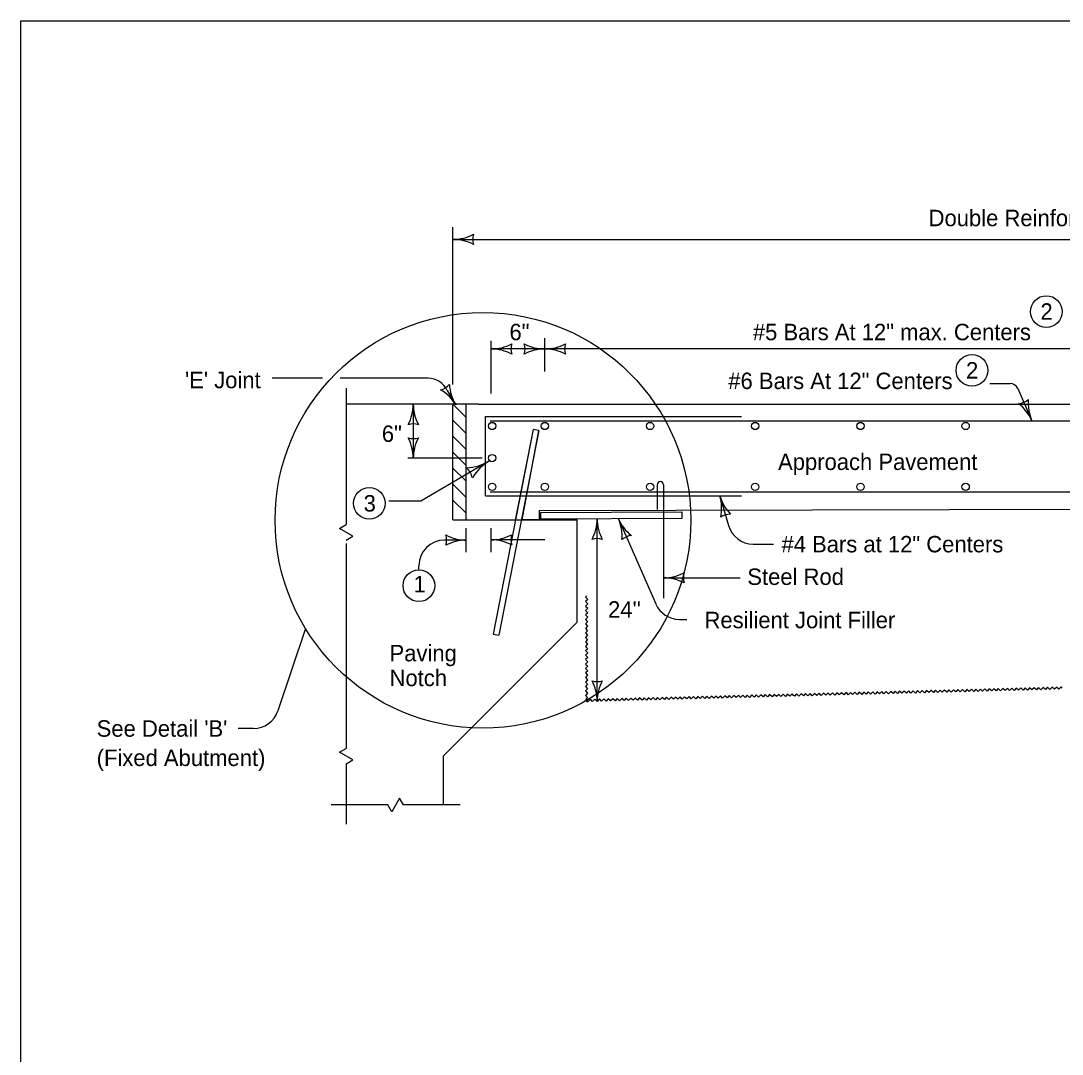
# Model space of a CAD drawing. Extents: x -2134934 to -2124557, y -2139046 to -2134021.
# Drawn here: x -2134934 to -2133922, y -2138041 to -2137036 of the extents above; entities that cross this region are included whole.
import ezdxf

# ---------------------------------------------------------------- set-up
doc = ezdxf.new("R2010")
doc.units = 0
for name, color, linetype in [('BridgeSuperStructureExisting', 7, 'Continuous'), ('dsnAlignmentStation', 7, 'Continuous'), ('dsnCellElements', 7, 'Continuous'), ('dsnStdLabel', 7, 'Continuous'), ('dsnTextFinalPlan', 7, 'Continuous')]:
    doc.layers.add(name, color=color, linetype=linetype)

msp = doc.modelspace()

# ---------------------------------------------------------------- linework, layer by layer
at = {"layer": 'BridgeSuperStructureExisting'}
for p, q in [((-2134618.2, -2137393.1), (-2134618.2, -2137432.3)), ((-2134519.9, -2137395.6), (-2134511.6, -2137409.3)), ((-2134489.3, -2137408.7), (-2134618.2, -2137408.7)), ((-2134514.3, -2137521.3), (-2134514.3, -2137408.7)), ((-2134501.4, -2137421.6), (-2134514.3, -2137408.7)), ((-2134489.3, -2137408.7), (-2133870.3, -2137408.7)), ((-2134501.4, -2137437.2), (-2134514.3, -2137424.3)), ((-2134482.7, -2137420.8), (-2134233.8, -2137420.8)), ((-2134482.7, -2137498), (-2134482.7, -2137420.8)), ((-2134478.1, -2137425), (-2133870.3, -2137425)), ((-2134618.2, -2137432.3), (-2134618.2, -2137525.8)), ((-2134501.4, -2137452.7), (-2134514.3, -2137439.9)), ((-2134501.4, -2137468.3), (-2134514.3, -2137455.4)), ((-2134501.4, -2137483.8), (-2134514.3, -2137471)), ((-2134501.4, -2137499.4), (-2134514.3, -2137486.5)), ((-2134482.7, -2137498), (-2134233.8, -2137498)), ((-2134478.1, -2137494), (-2133870.3, -2137494)), ((-2134501.4, -2137514.9), (-2134514.3, -2137502.1)), ((-2133870.3, -2137511), (-2134430.5, -2137512.5)), ((-2134428.7, -2137514), (-2134291.8, -2137513.5)), ((-2134428.7, -2137520.5), (-2134428.7, -2137514)), ((-2134291.8, -2137513.5), (-2134291.8, -2137520)), ((-2134514.3, -2137521.3), (-2134393.5, -2137521.3)), ((-2134291.8, -2137520), (-2134428.7, -2137520.5)), ((-2134393.5, -2137620.9), (-2134393.5, -2137521.3)), ((-2134618.2, -2137544.4), (-2134618.2, -2137743.5)), ((-2134523.4, -2137750.7), (-2134393.5, -2137620.9)), ((-2134523.4, -2137798.6), (-2134523.4, -2137750.7)), ((-2134618.2, -2137758.6), (-2134618.2, -2137817.4)), ((-2134577.5, -2137798.6), (-2134632.6, -2137798.6)), ((-2134507.3, -2137798.6), (-2134562.4, -2137798.6))]:
    msp.add_line(p, q, dxfattribs=at)
for points in [[(-2134618.2, -2137541), (-2134611.6, -2137537.2), (-2134624.7, -2137529.6), (-2134618.2, -2137525.9)], [(-2134618.2, -2137758.6), (-2134611.6, -2137754.8), (-2134624.7, -2137747.3), (-2134618.2, -2137743.5)], [(-2134562.4, -2137798.6), (-2134566.2, -2137792), (-2134573.8, -2137805.1), (-2134577.5, -2137798.6)]]:
    msp.add_lwpolyline(points, dxfattribs=at)
for centre, radius in [((-2133937.2, -2137318.7), 15.4), ((-2134009.6, -2137375.9), 15.4), ((-2134476.1, -2137430), 3.55), ((-2134424.9, -2137430), 3.55), ((-2134322.6, -2137430), 3.55), ((-2134220.3, -2137430), 3.55), ((-2134118, -2137430), 3.55), ((-2134015.7, -2137430), 3.55), ((-2134476.1, -2137489.1), 3.55), ((-2134424.9, -2137489.1), 3.55), ((-2134322.6, -2137489.1), 3.55), ((-2134220.3, -2137489.1), 3.55), ((-2134118, -2137489.1), 3.55), ((-2134015.7, -2137489.1), 3.55), ((-2134595.5, -2137505.2), 15.4), ((-2134547.4, -2137585.4), 15.4)]:
    msp.add_circle(centre, radius, dxfattribs=at)
for centre, radius, start, end in [((-2133965.9, -2137391.5), 16.9, 275.9068, 311.3735), ((-2133911.3, -2137407.5), 43.6, 175.5676, 203.6401), ((-2133991.2, -2137442.5), 43.6, 23.6401, 51.7126), ((-2134503.2, -2137422.2), 48.4, 272.4041, 300.4766), ((-2134454.1, -2137505.6), 48.4, 120.4766, 148.5491), ((-2134513.6, -2137484.5), 18.7, 12.7432, 48.2099), ((-2134222.3, -2137519.8), 25, 196.3264, 270), ((-2134522.4, -2137566), 25, 90, 180), ((-2134294.1, -2137593.1), 25, 203.6401, 270), ((-2134374, -2137662.2), 16.4, 252.2666, 287.7333), ((-2134416.5, -2137697.8), 42.5, 360, 28.0725), ((-2134331.5, -2137697.8), 42.5, 151.9275, 180), ((-2134708.2, -2137699.2), 25, 270, 341.4058)]:
    msp.add_arc(centre, radius, start, end, dxfattribs=at)
at = {"layer": 'dsnAlignmentStation'}
msp.add_lwpolyline([(-2134934.4, -2137035.9), (-2131799.4, -2137035.9), (-2131799.4, -2139045.9), (-2134934.4, -2139045.9)], close=True, dxfattribs=at)
at = {"layer": 'dsnCellElements'}
for centre, radius, start, end in [((-2134514.3, -2137206), 42.5, 270, 298.0725), ((-2134478.6, -2137248.5), 16.4, 162.2666, 197.7334), ((-2134514.3, -2137291), 42.5, 61.9275, 90), ((-2134477.1, -2137312.6), 42.5, 270, 298.0725), ((-2134477.1, -2137397.6), 42.5, 61.9275, 90), ((-2134441.5, -2137355.1), 16.4, 162.2666, 197.7334), ((-2134460.5, -2137355.1), 16.4, 342.2666, 17.7333), ((-2134424.9, -2137312.6), 42.5, 241.9275, 270), ((-2134424.9, -2137397.6), 42.5, 90, 118.0725), ((-2134424.9, -2137312.6), 42.5, 270, 298.0725), ((-2134424.9, -2137397.6), 42.5, 61.9275, 90), ((-2134389.3, -2137355.1), 16.4, 162.2666, 197.7334), ((-2134530.2, -2137378.9), 16.4, 283.7115, 319.1782), ((-2134547.8, -2137431.4), 42.5, 31.4449, 59.5174), ((-2134475.3, -2137387.1), 42.5, 183.3724, 211.4449), ((-2134595.3, -2137408.7), 42.5, 331.9275, 360), ((-2134510.3, -2137408.7), 42.5, 180, 208.0725), ((-2134552.8, -2137444.4), 16.4, 72.2666, 107.7334), ((-2134552.8, -2137425.8), 16.4, 252.2666, 287.7333), ((-2134595.3, -2137461.4), 42.5, 360, 28.0725), ((-2134510.3, -2137461.4), 42.5, 151.9275, 180), ((-2134213.9, -2137486.1), 42.5, 196.3264, 224.3989), ((-2134295.5, -2137509.9), 42.5, 348.2539, 16.3264), ((-2134244.7, -2137532.2), 16.4, 88.5931, 124.0598), ((-2134416.5, -2137520.3), 42.5, 331.9275, 360), ((-2134331.5, -2137520.3), 42.5, 180, 208.0725), ((-2134314.4, -2137503.2), 42.5, 203.6401, 231.7126), ((-2134392.3, -2137537.2), 42.5, 355.5676, 23.6401), ((-2134536.8, -2137541), 16.4, 342.2666, 17.7333), ((-2134501.2, -2137498.5), 42.5, 241.9275, 270), ((-2134477.1, -2137498.2), 42.5, 270, 298.0725), ((-2134441.5, -2137540.7), 16.4, 162.2666, 197.7334), ((-2134339, -2137552.8), 16.4, 95.9068, 131.3735), ((-2134501.2, -2137583.5), 42.5, 90, 118.0725), ((-2134477.1, -2137583.2), 42.5, 61.9275, 90), ((-2134374, -2137555.9), 16.4, 72.2666, 107.7334), ((-2134309.4, -2137535.1), 42.5, 270, 298.0725), ((-2134309.4, -2137620.1), 42.5, 61.9275, 90), ((-2134273.8, -2137577.6), 16.4, 162.2666, 197.7334)]:
    msp.add_arc(centre, radius, start, end, dxfattribs=at)
at = {"layer": 'dsnStdLabel'}
for p, q in [((-2134514.3, -2137355.4), (-2134514.3, -2137236.5)), ((-2134514.3, -2137248.5), (-2133142.6, -2137248.5)), ((-2134424.9, -2137377.1), (-2134424.9, -2137344.5)), ((-2134514.3, -2137389.8), (-2134514.3, -2137355.4)), ((-2134477.1, -2137398.4), (-2134477.1, -2137347.2)), ((-2134424.9, -2137355.1), (-2134477.1, -2137355.1)), ((-2133854.6, -2137355.1), (-2134424.9, -2137355.1)), ((-2134681.1, -2137383.5), (-2134690, -2137383.5)), ((-2134641.2, -2137383.5), (-2134681.1, -2137383.5)), ((-2134538.4, -2137383.5), (-2134623.8, -2137383.5)), ((-2133992.3, -2137388.7), (-2133972.5, -2137388.7)), ((-2133965, -2137393.5), (-2133951.3, -2137425)), ((-2134552.8, -2137408.7), (-2134552.8, -2137461.4)), ((-2134501.4, -2137521.3), (-2134501.4, -2137408.7)), ((-2134501.4, -2137521.3), (-2134501.4, -2137408.7)), ((-2134489.3, -2137408.7), (-2133870.3, -2137408.7)), ((-2134436.2, -2137433.3), (-2134475.3, -2137632.4)), ((-2134430.7, -2137434.4), (-2134469.7, -2137633.5)), ((-2134436.2, -2137433.3), (-2134453.6, -2137521.7)), ((-2134446.9, -2137521.3), (-2134430.7, -2137434.4)), ((-2134430.7, -2137434.4), (-2134436.2, -2137433.3)), ((-2134430.7, -2137434.4), (-2134436.2, -2137433.3)), ((-2134485.8, -2137461.4), (-2134558, -2137461.4)), ((-2134478.6, -2137463.9), (-2134545.5, -2137503.2)), ((-2134254.7, -2137498), (-2134246.3, -2137526.8)), ((-2134545.5, -2137503.2), (-2134576.7, -2137503.2)), ((-2133870.3, -2137511), (-2134430.5, -2137512.5)), ((-2134430.5, -2137512.5), (-2134430.5, -2137521.3)), ((-2134430.5, -2137512.5), (-2134430.5, -2137521.3)), ((-2134428.7, -2137514), (-2134291.8, -2137513.5)), ((-2134428.7, -2137520.5), (-2134428.7, -2137514)), ((-2134291.8, -2137513.5), (-2134291.8, -2137520)), ((-2134453.6, -2137521.7), (-2134501.4, -2137521.3)), ((-2134430.5, -2137521.3), (-2134446.9, -2137521.3)), ((-2134291.8, -2137520), (-2134428.7, -2137520.5)), ((-2134374, -2137697.8), (-2134374, -2137520.3)), ((-2134353.3, -2137520.2), (-2134317, -2137603.1)), ((-2134501.4, -2137552.7), (-2134501.4, -2137529.4)), ((-2134477.1, -2137552.8), (-2134477.1, -2137529.5)), ((-2134501.2, -2137541), (-2134522.4, -2137541)), ((-2134424.9, -2137540.7), (-2134477.1, -2137540.7)), ((-2134222.3, -2137544.8), (-2134202.5, -2137544.8)), ((-2134547.4, -2137570), (-2134547.4, -2137566)), ((-2134309.4, -2137577.6), (-2134235.1, -2137577.6)), ((-2134294.1, -2137618.1), (-2134286.9, -2137618.1)), ((-2134657.6, -2137627), (-2134684.5, -2137707.1)), ((-2134475.3, -2137632.4), (-2134469.7, -2137633.5)), ((-2134708.2, -2137724.2), (-2134723.2, -2137724.2))]:
    msp.add_line(p, q, dxfattribs=at)
for points in [[(-2134384.3, -2137595.3), (-2134385.4, -2137596.4), (-2134383.2, -2137598.6), (-2134385.4, -2137600.7), (-2134383.2, -2137602.9), (-2134385.4, -2137605.1), (-2134383.2, -2137607.3), (-2134385.4, -2137609.4), (-2134383.2, -2137611.6), (-2134385.4, -2137613.8), (-2134383.2, -2137616), (-2134385.4, -2137618.2), (-2134383.3, -2137620.4), (-2134385.4, -2137622.5), (-2134383.3, -2137624.7), (-2134385.5, -2137626.9), (-2134383.3, -2137629.1), (-2134385.5, -2137631.3), (-2134383.3, -2137633.4), (-2134385.5, -2137635.6), (-2134383.3, -2137637.8), (-2134385.5, -2137640), (-2134383.3, -2137642.2), (-2134385.5, -2137644.3), (-2134383.3, -2137646.5), (-2134384.4, -2137647.6)], [(-2134384.3, -2137647.4), (-2134385.4, -2137648.4), (-2134383.2, -2137650.6), (-2134385.4, -2137652.8), (-2134383.2, -2137655), (-2134385.4, -2137657.2), (-2134383.2, -2137659.3), (-2134385.4, -2137661.5), (-2134383.2, -2137663.7), (-2134385.4, -2137665.9), (-2134383.2, -2137668.1), (-2134385.4, -2137670.2), (-2134383.3, -2137672.4), (-2134385.4, -2137674.6), (-2134383.3, -2137676.8), (-2134385.5, -2137679), (-2134383.3, -2137681.1), (-2134385.5, -2137683.3), (-2134383.3, -2137685.5), (-2134385.5, -2137687.7), (-2134383.3, -2137689.9), (-2134385.5, -2137692), (-2134383.3, -2137694.2), (-2134385.5, -2137696.4), (-2134383.3, -2137698.6)], [(-2134183.3, -2137691.7), (-2134184.5, -2137690.6), (-2134186.6, -2137692.9), (-2134188.8, -2137690.7), (-2134190.9, -2137693), (-2134193.2, -2137690.9), (-2134195.3, -2137693.1), (-2134197.5, -2137691), (-2134199.7, -2137693.2), (-2134201.9, -2137691.1), (-2134204, -2137693.3), (-2134206.3, -2137691.2), (-2134208.4, -2137693.4), (-2134210.6, -2137691.3), (-2134212.7, -2137693.5), (-2134215, -2137691.4), (-2134217.1, -2137693.7), (-2134219.3, -2137691.5), (-2134221.5, -2137693.8), (-2134223.7, -2137691.6), (-2134225.8, -2137693.9), (-2134228.1, -2137691.8), (-2134230.2, -2137694), (-2134232.4, -2137691.9), (-2134234.5, -2137694.1), (-2134235.7, -2137693)], [(-2134131, -2137690.3), (-2134132.2, -2137689.3), (-2134134.3, -2137691.5), (-2134136.5, -2137689.4), (-2134138.6, -2137691.6), (-2134140.9, -2137689.5), (-2134143, -2137691.7), (-2134145.2, -2137689.6), (-2134147.4, -2137691.8), (-2134149.6, -2137689.7), (-2134151.7, -2137691.9), (-2134154, -2137689.8), (-2134156.1, -2137692.1), (-2134158.3, -2137689.9), (-2134160.4, -2137692.2), (-2134162.7, -2137690.1), (-2134164.8, -2137692.3), (-2134167, -2137690.2), (-2134169.2, -2137692.4), (-2134171.4, -2137690.3), (-2134173.5, -2137692.5), (-2134175.8, -2137690.4), (-2134177.9, -2137692.6), (-2134180.1, -2137690.5), (-2134182.2, -2137692.7), (-2134183.3, -2137691.7)], [(-2134078.7, -2137688.9), (-2134079.9, -2137687.9), (-2134082, -2137690.1), (-2134084.2, -2137688), (-2134086.3, -2137690.2), (-2134088.6, -2137688.1), (-2134090.7, -2137690.4), (-2134092.9, -2137688.2), (-2134095.1, -2137690.5), (-2134097.3, -2137688.3), (-2134099.4, -2137690.6), (-2134101.7, -2137688.5), (-2134103.8, -2137690.7), (-2134106, -2137688.6), (-2134108.1, -2137690.8), (-2134110.4, -2137688.7), (-2134112.5, -2137690.9), (-2134114.7, -2137688.8), (-2134116.8, -2137691), (-2134119.1, -2137688.9), (-2134121.2, -2137691.2), (-2134123.4, -2137689), (-2134125.6, -2137691.3), (-2134127.8, -2137689.1), (-2134129.9, -2137691.4), (-2134131, -2137690.3)], [(-2134026.4, -2137687.6), (-2134027.5, -2137686.5), (-2134029.7, -2137688.8), (-2134031.9, -2137686.6), (-2134034, -2137688.9), (-2134036.3, -2137686.8), (-2134038.4, -2137689), (-2134040.6, -2137686.9), (-2134042.7, -2137689.1), (-2134045, -2137687), (-2134047.1, -2137689.2), (-2134049.3, -2137687.1), (-2134051.5, -2137689.3), (-2134053.7, -2137687.2), (-2134055.8, -2137689.4), (-2134058.1, -2137687.3), (-2134060.2, -2137689.6), (-2134062.4, -2137687.4), (-2134064.5, -2137689.7), (-2134066.8, -2137687.5), (-2134068.9, -2137689.8), (-2134071.1, -2137687.7), (-2134073.3, -2137689.9), (-2134075.5, -2137687.8), (-2134077.6, -2137690), (-2134078.7, -2137688.9)], [(-2133974.1, -2137686.2), (-2133975.2, -2137685.2), (-2133977.4, -2137687.4), (-2133979.6, -2137685.3), (-2133981.7, -2137687.5), (-2133984, -2137685.4), (-2133986.1, -2137687.6), (-2133988.3, -2137685.5), (-2133990.4, -2137687.7), (-2133992.7, -2137685.6), (-2133994.8, -2137687.8), (-2133997, -2137685.7), (-2133999.2, -2137688), (-2134001.4, -2137685.8), (-2134003.5, -2137688.1), (-2134005.8, -2137686), (-2134007.9, -2137688.2), (-2134010.1, -2137686.1), (-2134012.2, -2137688.3), (-2134014.5, -2137686.2), (-2134016.6, -2137688.4), (-2134018.8, -2137686.3), (-2134021, -2137688.5), (-2134023.2, -2137686.4), (-2134025.3, -2137688.6), (-2134026.4, -2137687.6)], [(-2133921.8, -2137684.9), (-2133922.9, -2137683.8), (-2133925.1, -2137686), (-2133927.3, -2137683.9), (-2133929.4, -2137686.1), (-2133931.7, -2137684), (-2133933.8, -2137686.3), (-2133936, -2137684.1), (-2133938.1, -2137686.4), (-2133940.4, -2137684.2), (-2133942.5, -2137686.5), (-2133944.7, -2137684.4), (-2133946.9, -2137686.6), (-2133949.1, -2137684.5), (-2133951.2, -2137686.7), (-2133953.5, -2137684.6), (-2133955.6, -2137686.8), (-2133957.8, -2137684.7), (-2133959.9, -2137686.9), (-2133962.2, -2137684.8), (-2133964.3, -2137687), (-2133966.5, -2137684.9), (-2133968.6, -2137687.2), (-2133970.9, -2137685), (-2133973, -2137687.3), (-2133974.1, -2137686.2)], [(-2134340.3, -2137695.8), (-2134341.4, -2137694.7), (-2134343.5, -2137697), (-2134345.7, -2137694.8), (-2134347.9, -2137697.1), (-2134350.1, -2137695), (-2134352.2, -2137697.2), (-2134354.5, -2137695.1), (-2134356.6, -2137697.3), (-2134358.8, -2137695.2), (-2134360.9, -2137697.4), (-2134363.2, -2137695.3), (-2134365.3, -2137697.5), (-2134367.5, -2137695.4), (-2134369.7, -2137697.6), (-2134371.9, -2137695.5), (-2134374, -2137697.8), (-2134376.3, -2137695.6), (-2134378.4, -2137697.9), (-2134380.6, -2137695.7), (-2134382.7, -2137698), (-2134383.8, -2137697)], [(-2134288, -2137694.4), (-2134289.1, -2137693.4), (-2134291.2, -2137695.6), (-2134293.4, -2137693.5), (-2134295.6, -2137695.7), (-2134297.8, -2137693.6), (-2134299.9, -2137695.8), (-2134302.2, -2137693.7), (-2134304.3, -2137695.9), (-2134306.5, -2137693.8), (-2134308.6, -2137696), (-2134310.9, -2137693.9), (-2134313, -2137696.2), (-2134315.2, -2137694), (-2134317.4, -2137696.3), (-2134319.6, -2137694.1), (-2134321.7, -2137696.4), (-2134324, -2137694.3), (-2134326.1, -2137696.5), (-2134328.3, -2137694.4), (-2134330.4, -2137696.6), (-2134332.7, -2137694.5), (-2134334.8, -2137696.7), (-2134337, -2137694.6), (-2134339.1, -2137696.8), (-2134340.3, -2137695.8)], [(-2134235.7, -2137693), (-2134236.8, -2137692), (-2134238.9, -2137694.2), (-2134241.1, -2137692.1), (-2134243.3, -2137694.3), (-2134245.5, -2137692.2), (-2134247.6, -2137694.5), (-2134249.9, -2137692.3), (-2134252, -2137694.6), (-2134254.2, -2137692.4), (-2134256.3, -2137694.7), (-2134258.6, -2137692.6), (-2134260.7, -2137694.8), (-2134262.9, -2137692.7), (-2134265, -2137694.9), (-2134267.3, -2137692.8), (-2134269.4, -2137695), (-2134271.6, -2137692.9), (-2134273.8, -2137695.1), (-2134276, -2137693), (-2134278.1, -2137695.2), (-2134280.4, -2137693.1), (-2134282.5, -2137695.4), (-2134284.7, -2137693.2), (-2134286.8, -2137695.5), (-2134288, -2137694.4)]]:
    msp.add_lwpolyline(points, dxfattribs=at)
for centre, radius in [((-2134485.1, -2137521.7), 202.1), ((-2134476.1, -2137461.2), 3.55)]:
    msp.add_circle(centre, radius, dxfattribs=at)
for centre, radius in [((-2134538.4, -2137403.7), 20.2), ((-2133972.5, -2137396.8), 8.08)]:
    msp.add_arc(centre, radius, 23.6401, 90, dxfattribs=at)
at = {"layer": 'dsnTextFinalPlan'}
for p, q in [((-2134315.7, -2137487.2), (-2134315.7, -2137511.3)), ((-2134309.4, -2137487.2), (-2134309.4, -2137597.4))]:
    msp.add_line(p, q, dxfattribs=at)
msp.add_arc((-2134312.6, -2137487.2), 3.15, 0, 180, dxfattribs=at)

# ---------------------------------------------------------------- texts
at = {"layer": 'dsnStdLabel'}
for s, p in [('Double Reinforced Section (20\'-0" min.)', (-2134051.7, -2137235.7)), ('2', (-2133943, -2137326.7)), ('6"', (-2134459.3, -2137346.6)), ('#5 Bars At 12" max. Centers', (-2134222.6, -2137346.6)), ("'E' Joint", (-2134774.8, -2137393.3)), ('2', (-2134015.3, -2137383.9)), ('#6 Bars At 12" Centers', (-2134246.5, -2137394.1)), ('6"', (-2134583.4, -2137445.5)), ('Approach Pavement', (-2134198.1, -2137472.8)), ('3', (-2134601.1, -2137513.2)), ('#4 Bars at 12" Centers', (-2134194.8, -2137552.9)), ('Steel Rod', (-2134228, -2137584.6)), ('1', (-2134552.6, -2137591.8)), ("24''", (-2134363.4, -2137616.4)), ('Resilient Joint Filler', (-2134269.6, -2137626.7)), ('Paving', (-2134575.9, -2137658.9)), ('Notch', (-2134575.9, -2137683)), ("See Detail 'B'", (-2134860.7, -2137732.2)), ('(Fixed Abutment)', (-2134860.7, -2137760.7))]:
    msp.add_text(s, height=16, dxfattribs=at).set_placement(p)

doc.saveas('drawing.dxf')
